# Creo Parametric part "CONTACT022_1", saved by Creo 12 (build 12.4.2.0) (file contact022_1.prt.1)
Units: Custom; MM, KILOGRAM, SECS

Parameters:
  PTC_WM_ITERATION = "0"
  PTC_WM_VERSION = "-.0"
  PTC_WM_LIFECYCLE_STATE = "In Work"
  PTC_WM_LIFECYCLE = "MO_CADDocument"
  PTC_WM_CREATED_BY = "Maximilian Roepper (Z0017RMS: MO)"
  PTC_WM_CREATED_ON = "18-Sep-26 11:36:42 AM"
  PTC_WM_MODIFIED_BY = "Maximilian Roepper (Z0017RMS: MO)"
  PTC_WM_MODIFIED_ON = "18-Sep-26 11:36:46 AM"
  PDMLINKNUMBER = "PDM000071455202"
  PTC_WM_NAME = "contact022_1.prt"
  PTC_WM_NUMBER = "PDM000071455202"

Other parameters: WEIGHT, WEIGHT_FACTOR, WEIGHT_ADD, _MASS_TEMP, _DIFF_TEMP, MC_ERRORS, SUPPLIER

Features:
  1. coordinate system
  2. datum plane "PRT_YZ"
  3. datum plane "PRT_XY"
  4. datum plane "PRT_XZ"
  5. coordinate system
  6. datum axis
  7. datum axis
  8. datum axis
  9. coordinate system
  10. imported feature

Other named items: PRT, SIEMENS_MO, DRW_VIEW_ORG, PRT_X, PRT_Y, PRT_Z, CS0, ROUGH_GROB

Layers: 00_STD_CSYS-KSYS, 01_STD_PLANES-EBENEN, 02_STD_AXES-ACHSEN, 03_STD_CSYS-KSYS, 24_IMPORT_FEAT-IMPORT_KE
